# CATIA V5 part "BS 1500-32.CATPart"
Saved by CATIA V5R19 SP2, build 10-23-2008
Part number: BS 1500-32
Bounding box of the stored display mesh (mm): x -31.459 to 31.459, y -31.459 to 31.459, z 0 to 108
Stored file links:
  C:\Users\Bora\Desktop\3D Katı model\BS serisi\BS 1500\BS 1500-32.CATPart
  C:\Program Files\Dassault Systemes\B19\intel_a\reffiles\standard\MetricThickPitch.txt
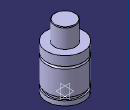
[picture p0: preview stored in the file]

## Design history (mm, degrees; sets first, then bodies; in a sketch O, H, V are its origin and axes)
Body1 (main body)
  Sketch1 on yz-plane, origin (0, 0, 0), H (0, 1, 0), V (0, 0, 1)
    point P1 (31.5, 59)
    point P2 (31.5, 55)
    point P3 (31.5, 59)
    point P7 (18, 107)
    point P9 (18, 107)
    point P14 (31.5, 55)
    arc A1 centre (31.5, 57) radius 2 from (31.5, 59) to (31.5, 55) ccw
    line L1 (31.5, 59) -> (31.5, 75)
    line L2 (31.5, 0) -> (31.5, 8)
    arc A2 centre (17, 107) radius 1 from (18, 107) to (17, 108) ccw
    line L3 (18, 107) -> (18, 75)
    line L4 (29, 13) -> (29, 8)
    line L5 (31.5, 13) -> (31.5, 55)
    line L6 (17, 108) -> (0, 108)
    point P15 (0, 108)
    line L7 (18, 75) -> (31.5, 75)
    line L8 (0, 0) -> (31.5, 0)
    line L9 (29, 13) -> (31.5, 13)
    line L10 (29, 8) -> (31.5, 8)
    tangency: L6 A2
    coincidence: P15 V, P1 P3, P2 P14, P7 P9
    horizontal: L7 H, L8 H, L9 H, L10 H
  Shaft1: profile Sketch1, axis Sketch1.V, angle 360
  Sketch2 on face of Shaft1 from Sketch1.L8, origin (0, 0, 0), H (1, 0, 0), V (0, -1, 0)
    point P1 (10, 0)
    distance P1 V = 10
  Hole1: placed by Sketch2, at (10, 0, 0) direction (0, 0, 1), diameter 6.647, depth 5, threaded "M8", thread diameter 8, thread depth 5, pitch 1.25
  CircPattern1: of Hole1, instances 2, angular step 180, axis from xy-plane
